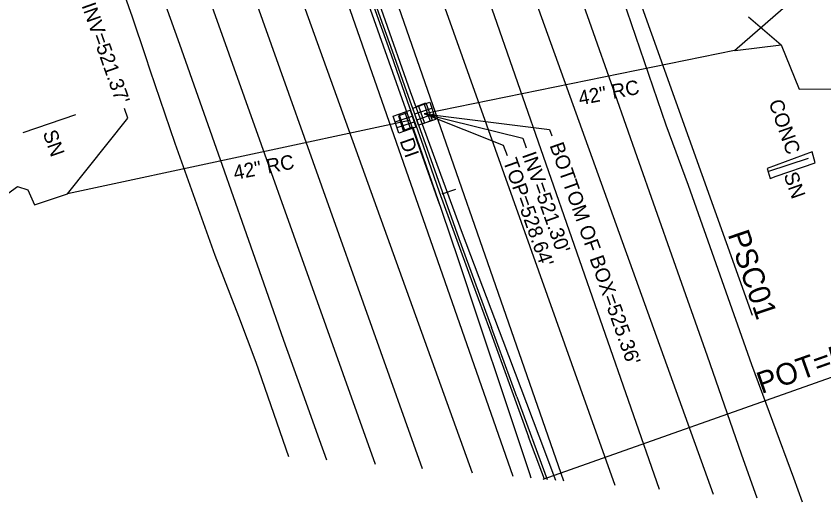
# Model space of a CAD drawing. Extents: x 2004847 to 2009016, y 1134161 to 1140101.
# Drawn here: x 2006823.5 to 2007047.7, y 1134161.4 to 1134296.2 of the extents above; entities that cross this region are included whole.
import ezdxf

# ---------------------------------------------------------------- set-up
doc = ezdxf.new("R2010")
doc.units = 0
for name, color, linetype in [('RD_DTM_BkLn1', 7, 'Continuous'), ('RD_EX_BldgApp', 7, 'Continuous'), ('RD_EX_Conc', 7, 'Continuous'), ('RD_EX_DR_Inlet', 7, 'Continuous'), ('RD_EX_DR_Pipe', 7, 'Continuous'), ('RD_EX_H2O', 7, 'Continuous'), ('RD_EX_Pavement_Markings', 7, 'Continuous'), ('RD_EX_Road', 7, 'Continuous'), ('RD_HC_Data', 7, 'Continuous'), ('RD_HC_Data_Tic', 7, 'Continuous'), ('RD_Sketch1', 7, 'Continuous'), ('RD_Sketch3', 7, 'Continuous')]:
    doc.layers.add(name, color=color, linetype=linetype)

msp = doc.modelspace()

# ---------------------------------------------------------------- linework, layer by layer
at = {"layer": 'RD_DTM_BkLn1'}
for points in [[(2006932.84, 1134275.32), (2006947.25, 1134235.99), (2006958.59, 1134206.13), (2006968.61, 1134179.74), (2006973.17, 1134167.41)], [(2006934.5, 1134271.09), (2006937.22, 1134272.17), (2006938.97, 1134267.33), (2006936.19, 1134266.19)], [(2006932.16, 1134269.4), (2006929.6, 1134268.52), (2006930.95, 1134264.43), (2006933.57, 1134265.49)]]:
    msp.add_lwpolyline(points, dxfattribs=at)
at = {"layer": 'RD_EX_BldgApp'}
for p, q in [((2006825.45, 1134263.93), (2006840.07, 1134268.87)), ((2006825.45, 1134263.93), (2006840.07, 1134268.87)), ((2006825.45, 1134263.93), (2006840.07, 1134268.87)), ((2007043.34, 1134256.67), (2007032.35, 1134253.06))]:
    msp.add_line(p, q, dxfattribs=at)
at = {"layer": 'RD_EX_Conc'}
for q in [(2006955.42, 1134209.78), (2006970.93, 1134167.61)]:
    msp.add_line((2006962.46, 1134190.5), q, dxfattribs=at)
for points in [[(2006919.51, 1134308.07), (2006920.82, 1134304.45), (2006923.64, 1134296.45), (2006927.56, 1134285.43), (2006932.01, 1134272.71), (2006936.44, 1134260.24), (2006940.93, 1134247.46), (2006945.08, 1134236.09), (2006950.19, 1134222.05), (2006954.91, 1134209.27), (2006960.74, 1134193.25), (2006965.74, 1134179.46)], [(2006920.2, 1134308.31), (2006921.18, 1134305.31), (2006924.56, 1134295.87), (2006927.84, 1134286.59), (2006931.89, 1134275.31), (2006936.52, 1134262.16), (2006946.37, 1134234.52), (2006955.42, 1134209.78)], [(2006970.16, 1134167.68), (2006969.41, 1134169.58), (2006965.74, 1134179.46)]]:
    msp.add_lwpolyline(points, dxfattribs=at)
msp.add_lwpolyline([(2007034.42, 1134251.74), (2007045.29, 1134255.51), (2007044.45, 1134258.5), (2007031.98, 1134253.93), (2007032.77, 1134251.16)], close=True, dxfattribs=at)
at = {"layer": 'RD_EX_DR_Inlet'}
for p, q in [((2006935.18, 1134271.21), (2006936.8, 1134266.48)), ((2006936.79, 1134271.76), (2006938.41, 1134267.03)), ((2006929.74, 1134269.02), (2006931.36, 1134264.29)), ((2006931.34, 1134269.57), (2006932.97, 1134264.84)), ((2006934.12, 1134269.05), (2006938.85, 1134270.67)), ((2006934.68, 1134267.44), (2006939.4, 1134269.06)), ((2006928.68, 1134266.86), (2006933.41, 1134268.48)), ((2006929.23, 1134265.25), (2006933.96, 1134266.88))]:
    msp.add_line(p, q, dxfattribs=at)
for points in [[(2006935.19, 1134265.93), (2006933.57, 1134270.66), (2006938.3, 1134272.28), (2006939.92, 1134267.55)], [(2006929.75, 1134263.74), (2006928.13, 1134268.47), (2006932.86, 1134270.09), (2006934.48, 1134265.36)]]:
    msp.add_lwpolyline(points, close=True, dxfattribs=at)
at = {"layer": 'RD_EX_DR_Pipe'}
for p, q in [((2007022.9, 1134286.65), (2006936.77, 1134269.12)), ((2006932.69, 1134267.2), (2006837.73, 1134246.91))]:
    msp.add_line(p, q, dxfattribs=at)
at = {"layer": 'RD_EX_H2O'}
for points in [[(2007026.77, 1134296.05), (2007035.85, 1134288.26)], [(2007023.1, 1134286.67), (2007035.85, 1134288.26), (2007040.81, 1134275.94), (2007068.13, 1134276.18), (2007090.11, 1134284.87)], [(2006659.86, 1134253.16), (2006701.99, 1134250.81), (2006743.45, 1134247.94), (2006782.32, 1134246.43), (2006817.4, 1134244.29), (2006823.92, 1134248.9), (2006826.73, 1134247.97), (2006828.62, 1134243.78), (2006837.73, 1134246.91)]]:
    msp.add_lwpolyline(points, dxfattribs=at)
at = {"layer": 'RD_EX_Pavement_Markings'}
for points in [[(2006761.15, 1134736.06), (2006771.82, 1134705.98), (2006777.23, 1134690.59), (2006790.01, 1134654.11), (2006795.73, 1134638.12), (2006808.48, 1134602.29), (2006810.13, 1134597.78), (2006815.7, 1134582.21), (2006823.33, 1134560.46), (2006837.37, 1134520.96), (2006843.05, 1134504.9), (2006850.38, 1134484.11), (2006854.57, 1134472.19), (2006861.41, 1134452.78), (2006871.77, 1134423.99), (2006878.28, 1134405.4), (2006883.4, 1134390.84), (2006889.14, 1134374.45), (2006894.32, 1134360.11), (2006902.43, 1134337.19), (2006906.68, 1134325.03), (2006910.08, 1134315.38), (2006961.34, 1134168.46)], [(2006743.96, 1134712.87), (2006747.16, 1134703.49), (2006757.16, 1134675.58), (2006760.38, 1134666.33), (2006770.51, 1134637.87), (2006773.91, 1134628.44), (2006783.92, 1134600.29), (2006787.22, 1134590.86), (2006797.43, 1134562.07), (2006800.7, 1134552.91), (2006810.57, 1134524.57), (2006813.83, 1134515.22), (2006823.78, 1134487.36), (2006827.07, 1134477.97), (2006836.8, 1134450.28), (2006840.09, 1134440.58), (2006849.89, 1134412.94), (2006853.18, 1134403.45), (2006863.05, 1134375.55), (2006866.41, 1134366.09), (2006876.69, 1134337.46), (2006880.32, 1134327.63), (2006936.22, 1134170.67)], [(2006732.74, 1134708.5), (2006736.01, 1134699.34), (2006746.11, 1134671.03), (2006749.58, 1134661.19), (2006759.46, 1134633.21), (2006762.72, 1134624.11), (2006773.08, 1134595.66), (2006776.33, 1134586.35), (2006786.48, 1134557.89), (2006789.7, 1134548.67), (2006799.21, 1134521.6), (2006802.52, 1134512.03), (2006812.88, 1134483.28), (2006816.15, 1134473.85), (2006825.71, 1134446.36), (2006828.93, 1134437.07), (2006838.79, 1134409.05), (2006842.06, 1134399.64), (2006851.92, 1134371.56), (2006855.13, 1134362.22), (2006865.49, 1134333.56), (2006868.8, 1134324.26), (2006923.13, 1134171.83)], [(2006883.84, 1134428.74), (2006897.79, 1134389.14), (2006902.5, 1134375.87), (2006907.19, 1134362.72), (2006911.63, 1134350.18), (2006919.19, 1134328.78), (2006922.45, 1134319.62), (2006975.43, 1134167.21)], [(2006823.72, 1134415.28), (2006828.76, 1134400.65), (2006832.7, 1134389.34), (2006835.66, 1134381.11), (2006838.78, 1134372.04), (2006843.25, 1134359.55), (2006847.6, 1134347.64), (2006852.54, 1134333.93), (2006856.67, 1134322.33), (2006860.39, 1134312.05), (2006864.92, 1134299.29), (2006868.8, 1134288.39)], [(2006914.12, 1134415.17), (2006919.32, 1134400.58), (2006922.62, 1134391.27), (2006927.45, 1134377.74), (2006932.28, 1134364.2), (2006935.81, 1134354.15), (2006940.59, 1134340.67), (2006945.38, 1134327.18), (2006946.92, 1134322.99), (2007001.97, 1134164.87)], [(2006903.58, 1134408.31), (2006909.45, 1134391.65), (2006912.75, 1134381.99), (2006916.96, 1134370.24), (2006921.16, 1134358.49), (2006924.62, 1134348.7), (2006929.38, 1134335.39), (2006934.14, 1134322.08), (2006935.3, 1134318.88), (2006989.68, 1134165.96)], [(2006865.02, 1134407.18), (2006869.79, 1134393.58), (2006874.56, 1134379.97), (2006877.97, 1134370.37), (2006882.97, 1134356.33), (2006887.96, 1134342.28), (2006891.36, 1134332.69), (2006950.11, 1134169.45)], [(2006930.07, 1134405.96), (2006933.59, 1134396.06), (2006938.51, 1134382.38), (2006943.42, 1134368.71), (2006946.73, 1134359.26), (2006951.69, 1134345.27), (2006956.65, 1134331.28), (2006958.15, 1134327.03), (2007017, 1134163.54)], [(2006971.5, 1134325.84), (2006982.51, 1134294.78), (2006989.62, 1134274.68), (2006995.78, 1134257.27), (2007005.91, 1134228.34), (2007015.25, 1134201.92), (2007024.74, 1134174.73), (2007029.06, 1134162.48)], [(2006868.8, 1134288.39), (2006880.67, 1134254.82), (2006886.75, 1134237.43), (2006892.76, 1134220.34), (2006897.7, 1134206.24), (2006902.58, 1134192.69), (2006907.57, 1134178.67), (2006909.63, 1134173.02)]]:
    msp.add_lwpolyline(points, dxfattribs=at)
at = {"layer": 'RD_EX_Road'}
for points in [[(2006817.28, 1134403.67), (2006822.12, 1134389.44), (2006827.23, 1134375.38), (2006832.39, 1134361.16), (2006837.52, 1134347.01), (2006842.51, 1134332.9), (2006847.61, 1134318.79), (2006852.69, 1134304.74), (2006855.68, 1134296.02), (2006859.43, 1134284.98)], [(2006910.32, 1134339.06), (2006910.74, 1134337.83), (2006915.85, 1134323.72), (2006917.85, 1134317.98), (2006932.84, 1134275.32)], [(2006940.98, 1134244.01), (2006915.11, 1134317.17), (2006913.22, 1134322.48), (2006908.23, 1134336.6), (2006907.86, 1134337.68)], [(2006981.75, 1134329.57), (2006983.57, 1134324.23), (2006993.04, 1134297.64), (2007003.84, 1134266), (2007009.98, 1134249.28), (2007027.62, 1134199.49), (2007039.25, 1134168.02), (2007041.62, 1134161.37)], [(2006859.43, 1134284.98), (2006860.63, 1134281.31), (2006867.53, 1134260.95), (2006878.67, 1134229.82), (2006885.18, 1134212.93), (2006890.04, 1134200.19), (2006899.14, 1134173.95)], [(2006933.57, 1134265.49), (2006933.79, 1134264.81), (2006941.57, 1134242.3), (2006946.26, 1134228.37), (2006951.68, 1134212.16), (2006959.52, 1134188.64), (2006965.97, 1134169.25), (2006966.39, 1134168.01)]]:
    msp.add_lwpolyline(points, dxfattribs=at)
at = {"layer": 'RD_HC_Data'}
for p, q in [((2006994.03, 1134307.6), (2007027.82, 1134213.17)), ((2006969.76, 1134167.71), (2007089.24, 1134209.98))]:
    msp.add_line(p, q, dxfattribs=at)
at = {"layer": 'RD_HC_Data_Tic'}
msp.add_line((2006941.76, 1134246.87), (2006945.53, 1134248.2), dxfattribs=at)
at = {"layer": 'RD_Sketch1'}
for points in [[(2007022.9, 1134286.65), (2007053.4, 1134313.31), (2007052.46, 1134315.98)], [(2006837.73, 1134246.91), (2006854.54, 1134267.88), (2006853.59, 1134270.57)], [(2006936.77, 1134269.12), (2006964.11, 1134262.33), (2006965.06, 1134259.67)], [(2006936.8, 1134269.06), (2006971.49, 1134264.78), (2006972.14, 1134262.96)], [(2006936.8, 1134269.06), (2006958.71, 1134260.42), (2006959.75, 1134257.51)]]:
    msp.add_lwpolyline(points, dxfattribs=at)

# ---------------------------------------------------------------- texts
at = {"layer": 'RD_HC_Data'}
for s, rotation, p in [('PSC01', 288.8025, (2007020.96, 1134235.63)), ('POT=591+83.96', 19.482, (2007030.37, 1134191.28))]:
    msp.add_text(s, height=6, rotation=rotation, dxfattribs=at).set_placement(p)
at = {"layer": 'RD_Sketch1'}
for s, rotation, p in [("INV=521.37'", 289.4494, (2006841.62, 1134299.16)), ('42" RC', 10.8443, (2006979.98, 1134271.45)), ('DI', 289.4494, (2006929.89, 1134261.58)), ("BOTTOM OF BOX=525.36'", 289.4494, (2006971.5, 1134260.35)), ("INV=521.30'", 289.4494, (2006963.85, 1134257.73)), ('42" RC', 10.8443, (2006884.21, 1134250.73)), ("TOP=528.64'", 289.4494, (2006958.6, 1134255.98))]:
    msp.add_text(s, height=4, rotation=rotation, dxfattribs=at).set_placement(p)
at = {"layer": 'RD_Sketch3'}
for s, p in [('CONC', (2007032.28, 1134272.29)), ('SN', (2006830.84, 1134263.81)), ('SN', (2006830.84, 1134263.81)), ('SN', (2006830.84, 1134263.81)), ('SN', (2007036.45, 1134252.14))]:
    msp.add_text(s, height=4, rotation=289.4494, dxfattribs=at).set_placement(p)

doc.saveas('drawing.dxf')
